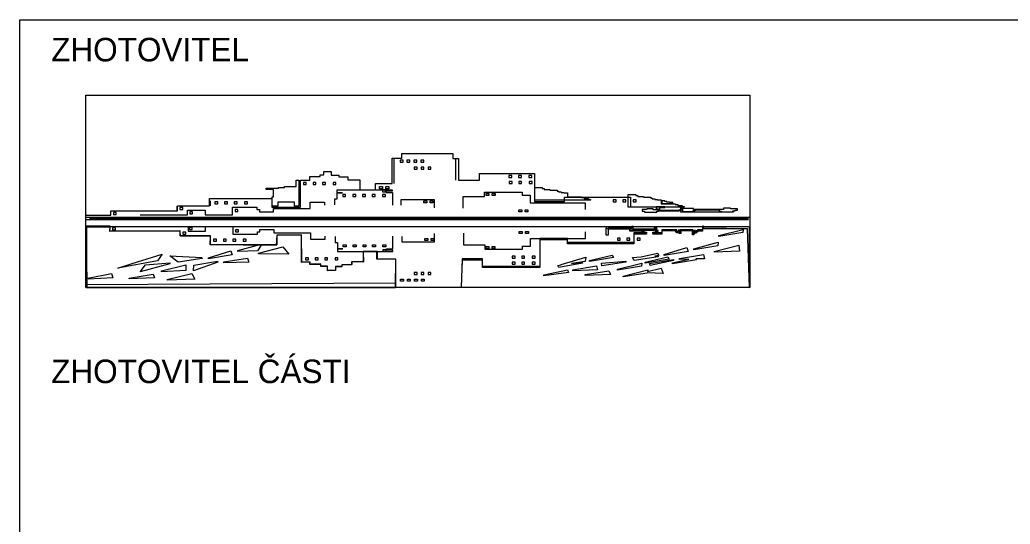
# Model space of a CAD drawing. Extents: x -740053 to -737481, y -1033516 to -1032488.
# Drawn here: x -737579.6 to -737548.07, y -1032916.58 to -1032900.51 of the extents above; entities that cross this region are included whole.
import ezdxf

# ---------------------------------------------------------------- set-up
doc = ezdxf.new("R2010")
doc.units = 0
doc.layers.add('promika-rozp', color=7, linetype='Continuous')

# ---------------------------------------------------------------- blocks, each defined once
blk = doc.blocks.new('onegast')
for p, q in [((22.998, 7.759), (22.998, 9.646)), ((27.598, 8.019), (27.598, 9.571)), ((6.825, 5.723), (6.825, 6.082)), ((9.252, 6.105), (9.252, 6.463)), ((9.309, 6.102), (9.309, 6.46)), ((0.046, 5.264), (49.513, 5.263)), ((0.278, 5.186), (49.435, 5.186)), ((0.046, 5.075), (49.427, 5.075)), ((0.046, 4.561), (49.435, 4.561))]:
    blk.add_line(p, q)
for points in [[(0, 14.352), (49.53, 14.352), (49.53, 0), (0, 0)], [(23.451, 9.351), (23.667, 9.351), (23.667, 9.502), (23.451, 9.502)], [(23.957, 9.351), (24.173, 9.351), (24.173, 9.502), (23.957, 9.502)], [(24.48, 9.351), (24.696, 9.351), (24.696, 9.502), (24.48, 9.502)], [(24.501, 8.843), (24.717, 8.843), (24.717, 8.994), (24.501, 8.994)], [(24.994, 9.351), (25.21, 9.351), (25.21, 9.502), (24.994, 9.502)], [(25.007, 8.843), (25.223, 8.843), (25.223, 8.994), (25.007, 8.994)], [(25.53, 8.843), (25.746, 8.843), (25.746, 8.994), (25.53, 8.994)], [(21.914, 7.53), (22.13, 7.53), (22.13, 7.378), (21.914, 7.378)], [(22.377, 7.53), (22.593, 7.53), (22.593, 7.378), (22.377, 7.378)], [(19.161, 6.799), (19.377, 6.799), (19.377, 6.95), (19.161, 6.95)], [(29.857, 7.022), (30.073, 7.022), (30.073, 6.871), (29.857, 6.871)], [(30.32, 7.022), (30.536, 7.022), (30.536, 6.871), (30.32, 6.871)], [(25.216, 6.462), (25.432, 6.462), (25.432, 6.311), (25.216, 6.311)], [(25.679, 6.462), (25.895, 6.462), (25.895, 6.311), (25.679, 6.311)], [(32.298, 5.793), (32.514, 5.793), (32.514, 5.642), (32.298, 5.642)], [(32.761, 5.793), (32.977, 5.793), (32.977, 5.642), (32.761, 5.642)], [(32.333, 4.18), (32.549, 4.18), (32.549, 4.029), (32.333, 4.029)], [(32.796, 4.18), (33.012, 4.18), (33.012, 4.029), (32.796, 4.029)], [(12.874, 2.574), (14.701, 3.028), (15.132, 2.483), (12.879, 2.512)], [(19.195, 3.182), (19.411, 3.182), (19.411, 3.031), (19.195, 3.031)], [(25.286, 3.656), (25.502, 3.656), (25.502, 3.505), (25.286, 3.505)], [(25.749, 3.656), (25.965, 3.656), (25.965, 3.505), (25.749, 3.505)], [(29.843, 3.074), (30.059, 3.074), (30.059, 2.923), (29.843, 2.923)], [(30.306, 3.074), (30.522, 3.074), (30.522, 2.923), (30.306, 2.923)], [(3.464, 1.792), (5.689, 2.483), (5.353, 1.985), (2.388, 1.451)], [(6.257, 2.359), (8.663, 2.239), (8.678, 2.175), (6.892, 1.886)], [(9.139, 2.21), (10.813, 2.729), (10.929, 2.436), (9.143, 2.148)], [(4.449, 1.687), (6.263, 1.842), (6.277, 1.778), (4.06, 1.174)], [(5.644, 1.239), (7.471, 1.693), (7.457, 1.283), (5.649, 1.176)], [(8.049, 1.674), (9.825, 1.965), (9.84, 1.9), (8.039, 1.247)], [(10.285, 1.911), (12.061, 2.202), (12.15, 1.899), (10.289, 1.849)], [(0.161, 0.692), (1.912, 1.059), (2.012, 0.718), (0.165, 0.63)], [(3.24, 0.71), (5.016, 1), (5.119, 0.715), (3.244, 0.648)], [(6.077, 0.602), (7.903, 1.057), (8.126, 0.622), (6.081, 0.54)], [(24.501, 0.974), (24.717, 0.974), (24.717, 1.125), (24.501, 1.125)], [(25.007, 0.974), (25.223, 0.974), (25.223, 1.125), (25.007, 1.125)], [(25.53, 0.974), (25.746, 0.974), (25.746, 1.125), (25.53, 1.125)], [(23.485, 0.631), (23.701, 0.631), (23.701, 0.48), (23.485, 0.48)], [(23.99, 0.631), (24.206, 0.631), (24.206, 0.48), (23.99, 0.48)], [(24.513, 0.631), (24.729, 0.631), (24.729, 0.48), (24.513, 0.48)], [(25.028, 0.631), (25.244, 0.631), (25.244, 0.48), (25.028, 0.48)]]:
    blk.add_lwpolyline(points, close=True)
for points in [[(0.046, 5.405), (1.862, 5.405), (1.862, 5.731), (6.84, 5.731), (6.84, 6.109), (9.238, 6.109), (9.238, 6.643), (13.878, 6.643), (13.878, 6.005), (16.015, 6.005), (16.015, 8.023), (16.706, 8.023), (16.706, 8.284), (17.475, 8.284), (17.475, 8.401), (17.749, 8.401), (17.749, 8.662), (18.296, 8.662), (18.296, 8.388), (18.879, 8.388), (18.879, 8.272), (19.556, 8.272), (19.556, 8.037), (20.443, 8.037), (20.443, 7.282), (21.616, 7.282), (21.616, 7.764), (22.841, 7.764), (22.841, 9.665), (23.57, 9.665), (23.57, 9.994), (27.389, 9.994), (27.389, 9.629), (27.806, 9.629), (27.806, 8.014), (29.37, 8.014), (29.37, 8.522), (33.462, 8.522), (33.462, 6.412), (35.707, 6.412), (35.707, 6.737), (40.62, 6.737), (40.62, 6.034), (44.351, 6.034), (44.351, 5.656), (48.313, 5.656)], [(31.563, 8.207), (31.779, 8.207), (31.779, 8.358), (31.563, 8.358), (31.563, 8.207)], [(32.276, 8.207), (32.493, 8.207), (32.493, 8.358), (32.276, 8.358), (32.276, 8.207)], [(33.049, 8.207), (33.265, 8.207), (33.265, 8.358), (33.049, 8.358), (33.049, 8.207)], [(14.328, 6.074), (13.905, 6.074), (13.905, 6.765), (14, 6.765), (14, 7.326), (13.453, 7.326), (13.453, 7.425), (14.378, 7.425), (14.378, 7.475), (14.825, 7.475), (14.825, 7.544), (15.233, 7.544), (15.273, 7.544), (15.68, 7.544), (15.68, 8.021), (15.879, 8.021), (15.879, 6.074), (15.571, 6.074), (15.571, 6.362), (14.328, 6.362), (14.328, 6.074)], [(16.228, 7.685), (16.444, 7.685), (16.444, 7.836), (16.228, 7.836), (16.228, 7.685)], [(16.952, 7.685), (17.168, 7.685), (17.168, 7.836), (16.952, 7.836), (16.952, 7.685)], [(17.666, 7.685), (17.882, 7.685), (17.882, 7.836), (17.666, 7.836), (17.666, 7.685)], [(18.439, 7.685), (18.655, 7.685), (18.655, 7.836), (18.439, 7.836), (18.439, 7.685)], [(31.581, 7.761), (31.797, 7.761), (31.797, 7.913), (31.581, 7.913), (31.581, 7.761)], [(32.295, 7.761), (32.511, 7.761), (32.511, 7.913), (32.295, 7.913), (32.295, 7.761)], [(33.067, 7.761), (33.284, 7.761), (33.284, 7.913), (33.067, 7.913), (33.067, 7.761)], [(37.637, 6.532), (33.482, 6.532), (33.482, 7.473), (34.037, 7.473), (34.037, 7.386), (34.193, 7.386), (34.193, 7.317), (34.616, 7.317), (34.616, 7.275), (35.159, 7.275), (35.159, 7.197), (35.257, 7.197), (35.257, 7.144), (35.467, 7.144), (35.467, 7.095), (35.652, 7.095), (35.652, 7.062), (35.94, 7.062), (35.94, 6.779), (36.976, 6.779), (36.976, 6.725), (37.165, 6.725), (37.165, 6.639), (37.502, 6.639), (37.502, 6.565), (37.637, 6.565), (37.637, 6.532)], [(18.576, 6.169), (18.576, 6.617), (18.746, 6.617), (18.746, 7.081), (19.149, 7.081), (19.149, 7.081), (18.746, 7.081), (18.746, 7.282), (22.862, 7.282), (22.862, 7.282), (22.862, 7.183), (22.396, 7.183), (22.396, 7.088), (22.871, 7.088), (22.871, 6.157)], [(19.919, 6.799), (20.135, 6.799), (20.135, 6.95), (19.919, 6.95), (19.919, 6.799)], [(20.644, 6.799), (20.86, 6.799), (20.86, 6.95), (20.644, 6.95), (20.644, 6.799)], [(21.358, 6.799), (21.574, 6.799), (21.574, 6.95), (21.358, 6.95), (21.358, 6.799)], [(22.13, 6.799), (22.346, 6.799), (22.346, 6.95), (22.13, 6.95), (22.13, 6.799)], [(22.141, 7.131), (22.357, 7.131), (22.357, 7.282), (22.141, 7.282), (22.141, 7.131)], [(28.148, 5.929), (28.148, 6.792), (28.724, 6.792), (28.724, 6.792), (29.741, 6.792), (29.741, 7.118), (30.144, 7.118), (30.144, 7.118), (30.97, 7.118), (30.97, 7.118), (32.543, 7.118), (32.543, 6.888), (33.138, 6.888), (33.138, 6.313), (37.246, 6.313), (37.246, 5.833)], [(40.466, 6.007), (40.466, 6.948), (41.021, 6.948), (41.021, 6.861), (41.177, 6.861), (41.177, 6.792), (41.6, 6.792), (41.6, 6.75), (42.143, 6.75), (42.143, 6.672), (42.241, 6.672), (42.241, 6.619), (42.451, 6.619), (42.451, 6.57), (42.636, 6.57), (42.636, 6.537), (42.924, 6.537), (42.924, 6.254), (43.96, 6.254), (43.96, 6.2), (44.149, 6.2), (44.149, 6.114), (44.486, 6.114), (44.486, 6.04), (44.622, 6.04), (44.622, 6.007), (40.466, 6.007)], [(44.622, 6.007), (40.466, 6.007), (40.466, 6.948), (41.021, 6.948), (41.021, 6.861), (41.177, 6.861), (41.177, 6.792), (41.6, 6.792), (41.6, 6.75), (42.143, 6.75), (42.143, 6.672), (42.241, 6.672), (42.241, 6.619), (42.451, 6.619), (42.451, 6.57), (42.636, 6.57), (42.636, 6.537), (42.924, 6.537), (42.924, 6.254), (43.96, 6.254), (43.96, 6.2), (44.149, 6.2), (44.149, 6.114), (44.486, 6.114), (44.486, 6.04), (44.622, 6.04), (44.622, 6.007)], [(4.051, 5.42), (7.596, 5.42), (7.596, 5.765), (8.897, 5.765), (8.897, 5.42), (10.933, 5.42), (10.933, 6.01), (12.761, 6.01), (12.761, 5.826), (12.957, 5.826), (12.957, 5.643), (14, 5.643), (14, 5.888), (16.736, 5.888), (16.736, 6.366), (17.815, 6.366), (17.815, 6.145)], [(7.024, 5.813), (7.24, 5.813), (7.24, 5.964), (7.024, 5.964), (7.024, 5.813)], [(9.628, 6.243), (9.844, 6.243), (9.844, 6.394), (9.628, 6.394), (9.628, 6.243)], [(10.353, 6.243), (10.569, 6.243), (10.569, 6.394), (10.353, 6.394), (10.353, 6.243)], [(11.067, 6.243), (11.283, 6.243), (11.283, 6.394), (11.067, 6.394), (11.067, 6.243)], [(11.839, 6.243), (12.055, 6.243), (12.055, 6.394), (11.839, 6.394), (11.839, 6.243)], [(23.534, 6.16), (23.534, 6.579), (25.98, 6.579), (25.98, 5.951)], [(39.341, 6.398), (39.557, 6.398), (39.557, 6.549), (39.341, 6.549), (39.341, 6.398)], [(40.055, 6.398), (40.271, 6.398), (40.271, 6.549), (40.055, 6.549), (40.055, 6.398)], [(40.827, 6.398), (41.043, 6.398), (41.043, 6.549), (40.827, 6.549), (40.827, 6.398)], [(41.512, 5.831), (41.512, 5.707), (41.669, 5.707), (41.669, 5.636), (42.598, 5.636), (42.598, 5.694), (42.709, 5.694), (42.709, 5.727), (44.282, 5.727), (44.282, 5.811), (44.431, 5.811), (44.431, 5.844), (44.516, 5.844), (44.516, 5.681), (45.309, 5.681), (45.309, 5.74), (45.433, 5.74), (45.433, 5.779), (45.491, 5.779), (45.491, 5.805), (47.253, 5.805), (47.253, 5.707), (47.396, 5.707), (47.396, 5.649), (48.254, 5.649), (48.254, 5.727), (48.443, 5.727), (48.443, 5.785), (48.599, 5.785), (48.599, 5.87), (48.098, 5.87), (48.098, 5.922), (47.578, 5.922), (47.578, 5.831), (45.335, 5.831), (45.335, 5.902), (44.425, 5.902), (44.425, 5.772), (44.282, 5.772), (44.282, 5.746), (42.702, 5.746), (42.702, 5.811), (42.826, 5.811), (42.826, 5.967), (43.196, 5.967), (43.196, 6.019), (42.546, 6.019), (42.546, 5.863), (42.683, 5.863), (42.683, 5.798), (42.332, 5.798), (42.332, 5.87), (41.838, 5.87), (41.838, 5.824), (41.512, 5.831)], [(44.282, 5.727), (44.282, 5.746), (42.702, 5.746), (42.702, 5.811), (42.826, 5.811), (42.826, 5.967), (43.196, 5.967), (43.196, 6.019), (42.546, 6.019), (42.546, 5.863), (42.683, 5.863), (42.683, 5.798), (42.332, 5.798), (42.332, 5.87), (41.838, 5.87), (41.838, 5.824), (41.512, 5.831), (41.512, 5.707), (41.669, 5.707), (41.669, 5.636), (42.598, 5.636), (42.598, 5.694), (42.709, 5.694), (42.709, 5.727), (44.282, 5.727)], [(42.958, 6.466), (42.958, 6.276), (43.791, 6.276), (43.791, 6.348), (43.516, 6.348), (43.516, 6.365), (43.342, 6.365), (43.342, 6.413), (43.192, 6.413), (43.192, 6.466), (42.958, 6.466)], [(43.192, 6.466), (42.958, 6.466), (42.958, 6.276), (43.791, 6.276), (43.791, 6.348), (43.516, 6.348), (43.516, 6.365), (43.342, 6.365), (43.342, 6.413), (43.192, 6.413), (43.192, 6.466)], [(44.425, 5.902), (44.425, 5.811), (44.431, 5.811), (44.431, 5.844), (44.516, 5.844), (44.516, 5.681), (45.309, 5.681), (45.309, 5.74), (45.433, 5.74), (45.433, 5.779), (45.491, 5.779), (45.491, 5.805), (47.253, 5.805), (47.253, 5.707), (47.396, 5.707), (47.396, 5.649), (48.254, 5.649), (48.254, 5.727), (48.443, 5.727), (48.443, 5.785), (48.599, 5.785), (48.599, 5.87), (48.098, 5.87), (48.098, 5.922), (47.578, 5.922), (47.578, 5.831), (45.335, 5.831), (45.335, 5.902), (44.425, 5.902)], [(2.06, 5.439), (2.276, 5.439), (2.276, 5.591), (2.06, 5.591), (2.06, 5.439)], [(7.749, 5.505), (7.965, 5.505), (7.965, 5.656), (7.749, 5.656), (7.749, 5.505)], [(11.131, 5.681), (11.348, 5.681), (11.348, 5.832), (11.131, 5.832), (11.131, 5.681)], [(44.425, 5.772), (44.425, 5.811), (44.282, 5.811), (44.282, 5.772), (44.425, 5.772)], [(0.02, 0.014), (23.093, 0.002), (23.125, 2.114), (22.3, 2.114), (21.766, 2.106), (21.766, 2.114), (21.714, 2.114), (21.714, 2.69), (20.694, 2.699), (20.694, 2.513), (20.708, 1.897), (19.841, 1.924), (19.841, 1.714), (19.819, 1.714), (19.819, 1.69), (19.163, 1.69), (19.103, 1.687), (19.103, 1.544), (18.635, 1.544), (18.625, 1.386), (18.625, 1.266), (18.256, 1.266), (18.026, 1.258), (18.017, 1.57), (17.525, 1.57), (17.525, 1.716), (16.716, 1.716), (16.716, 1.896), (16.101, 1.86), (16.101, 1.902), (16.093, 1.902), (16.093, 2.719), (16.083, 3.915), (14.514, 3.915), (14.249, 3.911), (14.237, 3.714), (14.237, 3.187), (14.206, 3.187), (14.203, 3.146), (13.089, 3.156), (12.812, 2.735), (11.338, 2.693), (11.334, 2.755), (12.803, 3.159), (9.776, 3.187), (9.292, 3.187), (9.292, 3.191), (9.287, 3.191), (9.292, 3.593), (9.292, 3.82), (7.066, 3.831), (7.065, 3.849), (7.039, 3.849), (7.039, 4.196), (2.893, 4.204), (2.028, 4.198), (1.802, 4.187), (1.803, 4.196), (1.802, 4.196), (1.81, 4.518), (0.042, 4.506), (0.02, 0.014)], [(0.042, 4.506), (0.03, 0.238), (23.125, 0.347), (23.125, 2.125), (21.766, 2.106), (21.748, 2.69), (20.689, 2.699), (20.708, 1.897), (19.841, 1.924), (19.841, 1.714), (19.093, 1.687), (19.093, 1.559), (18.637, 1.568), (18.619, 1.277), (18.026, 1.258), (18.017, 1.605), (17.542, 1.596), (17.542, 1.769), (16.721, 1.751), (16.73, 1.897), (16.101, 1.86), (16.083, 3.939), (14.249, 3.911), (14.203, 3.146), (9.287, 3.191), (9.296, 3.82), (7.066, 3.831), (7.048, 4.196), (2.185, 4.205), (1.802, 4.187), (1.821, 4.518), (0.042, 4.506)], [(0.036, 4.579), (0.065, 0.028), (23.119, 0.038), (23.133, 2.114), (21.714, 2.114), (21.714, 2.699), (20.694, 2.699), (20.694, 1.928), (19.819, 1.928), (19.819, 1.69), (19.103, 1.69), (19.103, 1.544), (18.625, 1.544), (18.625, 1.266), (18.029, 1.266), (18.029, 1.57), (17.525, 1.57), (17.525, 1.716), (16.716, 1.716), (16.716, 1.902), (16.093, 1.902), (16.093, 3.915), (14.237, 3.915), (14.237, 3.187), (9.292, 3.187), (9.292, 3.849), (7.039, 3.849), (7.039, 4.233), (1.802, 4.196), (1.811, 4.57), (0.036, 4.579)], [(1.994, 4.298), (2.21, 4.298), (2.21, 4.449), (1.994, 4.449), (1.994, 4.298)], [(4.084, 4.561), (7.63, 4.561), (7.63, 4.216), (8.93, 4.216), (8.93, 4.561), (10.967, 4.561), (10.967, 3.971), (12.794, 3.971), (12.794, 4.155), (12.991, 4.155), (12.991, 4.339), (14.034, 4.339), (14.034, 4.094), (16.769, 4.094), (16.769, 3.616), (17.849, 3.616), (17.849, 3.836)], [(7.727, 4.32), (7.943, 4.32), (7.943, 4.471), (7.727, 4.471), (7.727, 4.32)], [(28.067, 2.05), (27.99, 0.054), (49.512, 0.016), (49.361, 4.382), (46.076, 4.382), (46.076, 4.478), (46.005, 4.478), (46.005, 4.215), (45.632, 4.215), (45.632, 4.138), (45.529, 4.138), (45.529, 4.054), (45.349, 4.054), (45.349, 3.945), (45.259, 3.945), (45.259, 4.099), (45.439, 4.054), (45.439, 4.129), (45.439, 4.133), (45.471, 4.133), (45.471, 4.178), (45.282, 4.178), (45.282, 4.224), (44.334, 4.224), (44.334, 4.182), (44.184, 4.182), (44.184, 4.122), (44.287, 4.122), (44.287, 4.084), (44.394, 4.084), (44.394, 4.026), (44.258, 4.026), (44.258, 4.073), (44.068, 4.073), (44.068, 4.127), (44.012, 4.127), (44.012, 4.173), (44.086, 4.173), (44.086, 4.227), (42.971, 4.227), (42.971, 3.984), (42.289, 3.984), (42.289, 4.035), (42.5, 4.035), (42.5, 4.084), (42.652, 4.084), (42.652, 4.131), (42.701, 4.131), (42.701, 4.178), (42.514, 4.178), (42.514, 4.235), (42.596, 4.235), (42.596, 4.367), (42.482, 4.367), (42.482, 4.433), (42.389, 4.433), (42.389, 4.269), (40.819, 4.269), (40.819, 4.456), (40.717, 4.456), (40.717, 4.402), (40.569, 4.402), (40.569, 4.429), (38.993, 4.429), (38.993, 4.376), (38.881, 4.376), (38.881, 4.427), (38.792, 4.427), (38.792, 3.942), (38.993, 3.942), (38.993, 4.374), (40.564, 4.374), (40.564, 4.225), (41.633, 4.225), (41.633, 4.187), (41.484, 4.187), (41.484, 4.078), (41.635, 4.078), (41.635, 4.029), (41.831, 4.029), (41.831, 3.98), (40.874, 3.98), (40.874, 3.262), (35.926, 3.262), (35.926, 3.569), (33.862, 3.569), (33.862, 1.483), (29.594, 1.483), (29.594, 2.051), (28.067, 2.05)], [(28.067, 2.141), (27.991, 0.053), (49.525, -0.002), (49.509, 4.521), (46.076, 4.473), (46.076, 4.57), (46.005, 4.57), (46.005, 4.306), (45.632, 4.306), (45.632, 4.229), (45.529, 4.229), (45.529, 4.146), (45.439, 4.146), (45.349, 4.146), (45.349, 4.036), (45.259, 4.036), (45.259, 4.191), (45.439, 4.146), (45.439, 4.22), (45.439, 4.224), (45.471, 4.224), (45.471, 4.269), (45.282, 4.269), (45.282, 4.316), (44.334, 4.316), (44.334, 4.273), (44.184, 4.273), (44.184, 4.213), (44.287, 4.213), (44.287, 4.176), (44.394, 4.176), (44.394, 4.118), (44.258, 4.118), (44.258, 4.164), (44.068, 4.164), (44.068, 4.218), (44.012, 4.218), (44.012, 4.265), (44.086, 4.265), (44.086, 4.318), (42.971, 4.318), (42.971, 4.076), (42.289, 4.076), (42.289, 4.126), (42.5, 4.126), (42.5, 4.175), (42.652, 4.175), (42.652, 4.222), (42.701, 4.222), (42.701, 4.269), (42.514, 4.269), (42.514, 4.327), (42.596, 4.327), (42.596, 4.458), (42.482, 4.458), (42.482, 4.525), (42.389, 4.525), (42.389, 4.36), (40.819, 4.36), (40.819, 4.547), (40.717, 4.547), (40.717, 4.494), (40.569, 4.494), (40.569, 4.52), (38.993, 4.52), (38.993, 4.465), (40.564, 4.465), (40.564, 4.316), (41.633, 4.316), (41.633, 4.278), (41.484, 4.278), (41.484, 4.169), (41.635, 4.169), (41.635, 4.12), (41.831, 4.12), (41.831, 4.071), (40.874, 4.071), (40.874, 3.353), (35.926, 3.353), (35.926, 3.66), (33.862, 3.66), (33.862, 1.575), (29.594, 1.575), (29.594, 2.142), (28.067, 2.141)], [(7.243, 3.99), (7.46, 3.99), (7.46, 4.142), (7.243, 4.142), (7.243, 3.99)], [(11.175, 4.166), (11.391, 4.166), (11.391, 4.317), (11.175, 4.317), (11.175, 4.166)], [(18.61, 3.813), (18.61, 3.364), (18.78, 3.364), (18.78, 2.9), (19.182, 2.9), (19.182, 2.9), (18.78, 2.9), (18.78, 2.699), (22.895, 2.699), (22.895, 2.699), (22.895, 2.799), (22.429, 2.799), (22.429, 2.894), (22.904, 2.894), (22.904, 3.824)], [(23.568, 3.821), (23.568, 3.403), (26.014, 3.403), (26.014, 4.03)], [(28.182, 4.052), (28.182, 3.189), (28.757, 3.189), (28.757, 3.189), (29.775, 3.189), (29.775, 2.863), (30.178, 2.863), (30.178, 2.863), (31.003, 2.863), (31.003, 2.863), (32.577, 2.863), (32.577, 3.093), (33.172, 3.093), (33.172, 3.669), (37.279, 3.669), (37.279, 4.148)], [(49.007, 4.105), (47.221, 3.817), (47.216, 3.879), (49.043, 4.334), (49.007, 4.105)], [(9.536, 3.464), (9.752, 3.464), (9.752, 3.615), (9.536, 3.615), (9.536, 3.464)], [(10.26, 3.464), (10.476, 3.464), (10.476, 3.615), (10.26, 3.615), (10.26, 3.464)], [(10.974, 3.464), (11.19, 3.464), (11.19, 3.615), (10.974, 3.615), (10.974, 3.464)], [(11.746, 3.464), (11.963, 3.464), (11.963, 3.615), (11.746, 3.615), (11.746, 3.464)], [(15.132, 2.483), (12.879, 2.512), (12.874, 2.574), (14.701, 3.028), (15.132, 2.483)], [(19.195, 3.031), (19.195, 3.182), (19.411, 3.182), (19.411, 3.031), (19.195, 3.031)], [(20.169, 3.031), (19.953, 3.031), (19.953, 3.182), (20.169, 3.182), (20.169, 3.031)], [(20.893, 3.031), (20.677, 3.031), (20.677, 3.182), (20.893, 3.182), (20.893, 3.031)], [(21.607, 3.031), (21.391, 3.031), (21.391, 3.182), (21.607, 3.182), (21.607, 3.031)], [(22.38, 3.031), (22.164, 3.031), (22.164, 3.182), (22.38, 3.182), (22.38, 3.031)], [(39.65, 3.525), (39.866, 3.525), (39.866, 3.677), (39.65, 3.677), (39.65, 3.525)], [(40.364, 3.525), (40.58, 3.525), (40.58, 3.677), (40.364, 3.677), (40.364, 3.525)], [(41.136, 3.525), (41.352, 3.525), (41.352, 3.677), (41.136, 3.677), (41.136, 3.525)], [(44.937, 2.689), (43.151, 2.401), (43.147, 2.463), (44.821, 2.982), (44.937, 2.689)], [(47.132, 3.109), (45.346, 2.82), (45.342, 2.882), (47.162, 3.382), (47.132, 3.109)], [(48.753, 2.715), (46.887, 2.639), (46.882, 2.701), (48.709, 3.155), (48.753, 2.715)], [(2.388, 1.451), (3.464, 1.792), (5.689, 2.483), (5.353, 1.985), (2.388, 1.451)], [(6.892, 1.886), (6.257, 2.359), (8.663, 2.239), (8.678, 2.175), (6.892, 1.886)], [(9.143, 2.148), (9.139, 2.21), (10.813, 2.729), (10.929, 2.436), (9.143, 2.148)], [(22.39, 2.699), (22.174, 2.699), (22.174, 2.85), (22.39, 2.85), (22.39, 2.699)], [(31.804, 2.197), (32.02, 2.197), (32.02, 2.348), (31.804, 2.348), (31.804, 2.197)], [(32.518, 2.197), (32.734, 2.197), (32.734, 2.348), (32.518, 2.348), (32.518, 2.197)], [(33.29, 2.197), (33.506, 2.197), (33.506, 2.348), (33.29, 2.348), (33.29, 2.197)], [(37.045, 1.826), (35.275, 1.483), (35.212, 1.656), (35.458, 1.687), (35.456, 1.725), (37.304, 2.273), (37.246, 1.951), (36.232, 1.787), (37.03, 1.89), (37.045, 1.826)], [(39.361, 2.237), (37.575, 1.949), (37.57, 2.011), (39.263, 2.411), (39.361, 2.237)], [(42.686, 2.302), (40.9, 2.014), (40.791, 2.246), (41.431, 2.287), (42.647, 2.574), (42.745, 2.401), (42.436, 2.351), (42.671, 2.366), (42.686, 2.302)], [(43.522, 2.115), (41.736, 1.826), (41.732, 1.888), (43.425, 2.288), (43.522, 2.115)], [(45.555, 2.06), (43.769, 1.772), (43.765, 1.834), (44.98, 2.121), (44.297, 2.102), (44.293, 2.164), (46.069, 2.455), (46.158, 2.152), (45.513, 2.135), (45.555, 2.06)], [(4.06, 1.174), (4.449, 1.687), (6.263, 1.842), (6.277, 1.778), (4.06, 1.174)], [(5.649, 1.176), (5.644, 1.239), (7.471, 1.693), (7.457, 1.283), (5.649, 1.176)], [(8.039, 1.247), (8.049, 1.674), (9.825, 1.965), (9.84, 1.9), (8.039, 1.247)], [(10.289, 1.849), (10.285, 1.911), (12.061, 2.202), (12.15, 1.899), (10.289, 1.849)], [(16.383, 2.065), (16.599, 2.065), (16.599, 2.216), (16.383, 2.216), (16.383, 2.065)], [(17.107, 2.065), (17.324, 2.065), (17.324, 2.216), (17.107, 2.216), (17.107, 2.065)], [(17.821, 2.065), (18.037, 2.065), (18.037, 2.216), (17.821, 2.216), (17.821, 2.065)], [(18.594, 2.065), (18.81, 2.065), (18.81, 2.216), (18.594, 2.216), (18.594, 2.065)], [(31.804, 1.752), (32.02, 1.752), (32.02, 1.903), (31.804, 1.903), (31.804, 1.752)], [(32.518, 1.752), (32.734, 1.752), (32.734, 1.903), (32.518, 1.903), (32.518, 1.752)], [(33.29, 1.752), (33.506, 1.752), (33.506, 1.903), (33.29, 1.903), (33.29, 1.752)], [(38.172, 1.324), (36.328, 1.254), (36.324, 1.316), (38.1, 1.607), (38.172, 1.324)], [(40.285, 1.905), (38.499, 1.617), (38.457, 1.814), (40.271, 1.97), (40.285, 1.905)], [(41.443, 1.592), (39.657, 1.304), (39.653, 1.366), (41.479, 1.82), (41.443, 1.592)], [(43.848, 2.028), (42.108, 1.637), (42.057, 1.801), (43.833, 2.092), (43.848, 2.028)], [(0.165, 0.63), (0.161, 0.692), (1.912, 1.059), (2.012, 0.718), (0.165, 0.63)], [(3.244, 0.648), (3.24, 0.71), (5.016, 1), (5.119, 0.715), (3.244, 0.648)], [(6.081, 0.54), (6.077, 0.602), (7.903, 1.057), (8.126, 0.622), (6.081, 0.54)], [(35.996, 1.11), (34.173, 0.883), (34.169, 0.945), (35.92, 1.312), (35.996, 1.11)], [(39.127, 0.968), (37.252, 0.901), (37.248, 0.963), (39.024, 1.253), (39.127, 0.968)], [(41.875, 1.082), (40.089, 0.793), (40.085, 0.855), (41.911, 1.31), (41.894, 1.2), (42.92, 1.442), (43.064, 1.042), (41.875, 1.085), (41.875, 1.082)]]:
    blk.add_lwpolyline(points)

msp = doc.modelspace()

# ---------------------------------------------------------------- linework, layer by layer
at = {"layer": 'promika-rozp'}
msp.add_lwpolyline([(-737579.597, -1032921.012), (-737579.597, -1032900.512), (-737489.597, -1032900.512), (-737489.597, -1032921.012)], dxfattribs=at)

# ---------------------------------------------------------------- block references
at = {"xscale": 0.42674586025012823, "yscale": 0.42674586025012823, "rotation": 2.187095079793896e-11}
msp.add_blockref('onegast', (-737577.496, -1032909.041), dxfattribs=at)

# ---------------------------------------------------------------- texts
at = {"layer": 'promika-rozp'}
for s, p in [('ZHOTOVITEL', (-737578.599, -1032901.837)), ('ZHOTOVITEL ČÁSTI', (-737578.599, -1032912.087))]:
    msp.add_text(s, height=0.75, dxfattribs=at).set_placement(p)

doc.saveas('drawing.dxf')
